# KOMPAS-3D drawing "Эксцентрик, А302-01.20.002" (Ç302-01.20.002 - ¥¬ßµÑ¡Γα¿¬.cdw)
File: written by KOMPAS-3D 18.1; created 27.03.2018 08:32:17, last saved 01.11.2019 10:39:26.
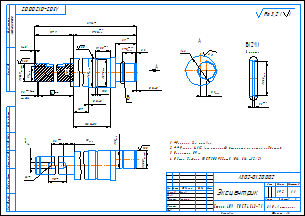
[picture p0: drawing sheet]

Sheet 1: A3, landscape

Document properties: Полное имя файла: D:\Мембранные насосы\Мембранный электропривод\А302-00.00.000 - ASTRA-302 (МЭ200)\А302-01.00.000 - Мембранный насос ASTRA-302-PVC\А302-01.20.002 - Эксцентрик.cdw; Масса: 1.91612

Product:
- Part/product: Эксцентрик  | designation А302-01.20.002
    Материал: Сталь 40Х  ГОСТ 4543-71 (density 7825 kg/m3)
    Масса: 1.91612
    Раздел спецификации: Детали
    Форматы листов документа: A3
    source file: \\192.168.87.28\Konstructor_doc\Мембранные насосы\Мембранный электропривод\А302-00.00.000 - ASTRA-302 (МЭ200)\3Д ПВХ\А302-01.20.002 - Эксцентрик.cdw

Title block, sheet 1: Наименование: Эксцентрик; designation: А302-01.20.002; Материал: Сталь 40Х  ГОСТ 4543-71; Масса: 1,92; scale: 1:1; Количество листов документа: 1; organisation: ЗАО «Астерион»; Форматы листов документа: A3; stored path: Z:\Мембранные насосы\Мембранный электропривод\А302-00.00.000 - ASTRA-302 (МЭ200)\Чертежи\А302-00.20.002 - Эксцентрик.cdw; Разработал: Милов; Т. контр.: Лучихин

Views: Вид 1, Вид:3, Проекционный вид 3, Местный разрез 1, Выносной элемент 4, Вид по стрелке 5, Выносной элемент Б, Выносной элемент, Вид:4
Referenced files in Z:\Мембранные насосы\Мембранный электропривод\А302-00.00.000 - ASTRA-302 (МЭ200)\3Д\: А302-00.20.002 - Эксцентрик.m3d
Referenced files in \\192.168.87.28\Konstructor_doc\Мембранные насосы\Мембранный электропривод\А302-00.00.000 - ASTRA-302 (МЭ200)\3Д ПВХ\: А302-01.20.002 - Эксцентрик.m3d
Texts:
  шайба
  Ra 3,2
  Ra 3,2 ( )
Dimensions and other numbers on the sheet: 8; 4; 82; 15; 90; 25; 1,25; 29; 1; 0,5; 21; 2,3; 17,5; 173,5; 291,4; 1,2; 107; 136,5±0,3; 40; 37,5; 39; 19,85; 117,9; 1,85; 3 места; 23,8; 1,3; 8,1; 42; 6,3; 1:1; 1,92

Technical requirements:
  *Размеры для справок.
  ** Размер L=112 (номинальный) уточнить по мотор редуктору.
  Покрытие: Ц9хр.
  Общие допуски ГОСТ 30893.2-mK (H14, h14,  t2/2).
